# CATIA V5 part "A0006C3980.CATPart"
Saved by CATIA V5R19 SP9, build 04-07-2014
Part number: A0006C3980
Bounding box of the stored display mesh (mm): x -14.996 to 14.996, y -14.951 to 14.951, z 0 to 85.069
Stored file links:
  O:\Catia Forum\A0006C3980.CATPart
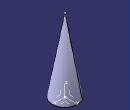
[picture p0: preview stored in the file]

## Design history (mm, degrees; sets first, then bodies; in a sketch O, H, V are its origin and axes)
AxisSystem1: origin (0, 0, 0), X (1, 0, 0), Y (0, 1, 0), Z (0, 0, 1)
Body1 (main body)
  Sketch1 on YZ plane of AxisSystem1, origin (0, 0, 0), H (0, 1, 0), V (0, 0, 1)
    axis line L1 (0, 0) -> (0, 85.0692)
    point P1 (0, 85.0692)
    line L2 (0, 0) -> (-15, 0)
    point P2 (-15, 0)
    line L3 (-15, 0) -> (0, 85.0692)
    point P3 (0, 85.0692)
    angle L3 L1 = 10
    "Radius" P2 L1 = 15
    vertical: L1 V
    horizontal: L2 H
    coincidence: P3 L1, L3 P1
  Shaft1: profile Sketch1, axis Sketch1.L1, angle 360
